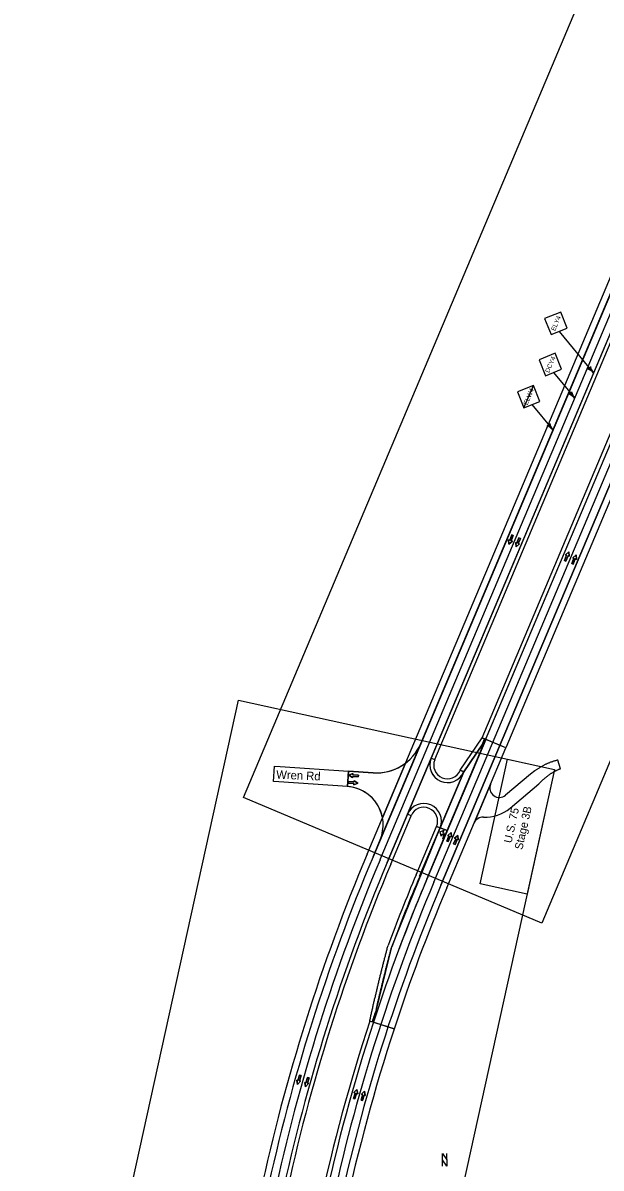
# Model space of a CAD drawing. Extents: x 14104283 to 14128447, y 8633203 to 8671666.
# Drawn here: x 14108596 to 14109499, y 8644945 to 8646734 of the extents above; entities that cross this region are included whole.
import ezdxf

# ---------------------------------------------------------------- set-up
doc = ezdxf.new("R2010")
doc.units = 0
for name, color, linetype in [('Cell', 7, 'Continuous'), ('Default', 7, 'Continuous'), ('dsnCellsNorthArrow', 7, 'Continuous'), ('dsnNonPlotable', 7, 'Continuous'), ('dsnPaintExistingBrokenLaneLineWhite', 7, 'Continuous'), ('dsnPaintExistingEdgeLineRightWhite', 7, 'Continuous'), ('dsnPaintExistingLaneLineWhite', 7, 'Continuous'), ('dsnPaintPlaceBrokenLineWhite', 7, 'Continuous'), ('dsnPaintPlaceEdgeLineLeftYellow', 7, 'Continuous'), ('dsnPaintPlaceEdgeLineRightWhite', 7, 'Continuous'), ('dsnShadingGranular', 7, 'Continuous'), ('dsnShadingPaved', 7, 'Continuous'), ('dsnStdLabel', 7, 'Continuous'), ('dsnStgShadingPrevPav', 7, 'Continuous'), ('dsnTextFinalPlan', 7, 'Continuous'), ('dsnTextOverlapEven', 7, 'Continuous')]:
    doc.layers.add(name, color=color, linetype=linetype)

msp = doc.modelspace()

# ---------------------------------------------------------------- linework, layer by layer
at = {"layer": 'Cell'}
for p, q in [((14109251.5, 8645469.4), (14109251.7, 8645469.4)), ((14109250.7, 8645466.9), (14109250.4, 8645467))]:
    msp.add_line(p, q, dxfattribs=at)
for points in [[(14109359.3, 8645933.9), (14109361.6, 8645933), (14109358.3, 8645924.9), (14109360.1, 8645924.2), (14109354.8, 8645919.6), (14109354.3, 8645926.5), (14109356, 8645925.8)], [(14109370.3, 8645929.5), (14109372.7, 8645928.6), (14109369.3, 8645920.5), (14109371.1, 8645919.8), (14109365.8, 8645915.2), (14109365.3, 8645922.2), (14109367, 8645921.4)], [(14109443.7, 8645893.2), (14109441.4, 8645894.2), (14109444.7, 8645902.3), (14109442.9, 8645903), (14109448.2, 8645907.6), (14109448.7, 8645900.6), (14109447, 8645901.3)], [(14109455, 8645888.4), (14109452.7, 8645889.4), (14109456, 8645897.5), (14109454.3, 8645898.2), (14109459.5, 8645902.8), (14109460.1, 8645895.8), (14109458.3, 8645896.5)], [(14109119.8, 8645558.6), (14109119.6, 8645556.1), (14109110.9, 8645556.8), (14109110.7, 8645554.9), (14109104.8, 8645558.6), (14109111.2, 8645561.2), (14109111.1, 8645559.3)], [(14109103.8, 8645546.5), (14109104, 8645549), (14109112.7, 8645548.3), (14109112.9, 8645550.1), (14109118.9, 8645546.5), (14109112.4, 8645543.9), (14109112.5, 8645545.8)], [(14109259.9, 8645454.9), (14109257.6, 8645455.8), (14109260.9, 8645463.9), (14109259.2, 8645464.6), (14109264.4, 8645469.2), (14109265, 8645462.3), (14109263.2, 8645463)], [(14109270.7, 8645450.4), (14109268.4, 8645451.3), (14109271.7, 8645459.4), (14109270, 8645460.1), (14109275.2, 8645464.7), (14109275.7, 8645457.7), (14109274, 8645458.5)], [(14109027.8, 8645090.4), (14109030.2, 8645089.7), (14109027.7, 8645081.3), (14109029.5, 8645080.7), (14109024.8, 8645075.6), (14109023.5, 8645082.5), (14109025.3, 8645082)], [(14109040.4, 8645086.8), (14109042.8, 8645086.1), (14109040.3, 8645077.7), (14109042.1, 8645077.2), (14109037.4, 8645072.1), (14109036.1, 8645078.9), (14109037.9, 8645078.4)], [(14109114.4, 8645053.2), (14109112, 8645054), (14109114.5, 8645062.3), (14109112.7, 8645062.9), (14109117.4, 8645068), (14109118.7, 8645061.1), (14109116.9, 8645061.6)], [(14109126.3, 8645050.6), (14109123.9, 8645051.3), (14109126.3, 8645059.7), (14109124.5, 8645060.3), (14109129.3, 8645065.4), (14109130.5, 8645058.5), (14109128.7, 8645059)]]:
    msp.add_lwpolyline(points, close=True, dxfattribs=at)
for points in [[(14109356, 8645925.8), (14109354.3, 8645926.5), (14109354.8, 8645919.6), (14109360.1, 8645924.2), (14109358.3, 8645924.9), (14109361.6, 8645933), (14109359.3, 8645933.9), (14109356, 8645925.8)], [(14109367, 8645921.4), (14109365.3, 8645922.2), (14109365.8, 8645915.2), (14109371.1, 8645919.8), (14109369.3, 8645920.5), (14109372.7, 8645928.6), (14109370.3, 8645929.5), (14109367, 8645921.4)], [(14109447, 8645901.3), (14109448.7, 8645900.6), (14109448.2, 8645907.6), (14109442.9, 8645903), (14109444.7, 8645902.3), (14109441.4, 8645894.2), (14109443.7, 8645893.2), (14109447, 8645901.3)], [(14109458.3, 8645896.5), (14109460.1, 8645895.8), (14109459.5, 8645902.8), (14109454.3, 8645898.2), (14109456, 8645897.5), (14109452.7, 8645889.4), (14109455, 8645888.4), (14109458.3, 8645896.5)], [(14109111.1, 8645559.3), (14109111.2, 8645561.2), (14109104.8, 8645558.6), (14109110.7, 8645554.9), (14109110.9, 8645556.8), (14109119.6, 8645556.1), (14109119.8, 8645558.6), (14109111.1, 8645559.3)], [(14109112.5, 8645545.8), (14109112.4, 8645543.9), (14109118.9, 8645546.5), (14109112.9, 8645550.1), (14109112.7, 8645548.3), (14109104, 8645549), (14109103.8, 8645546.5), (14109112.5, 8645545.8)], [(14109247.3, 8645470.5), (14109253, 8645472.8), (14109251.5, 8645469.4)], [(14109247.3, 8645470.5), (14109253, 8645472.8), (14109251.5, 8645469.4)], [(14109250.4, 8645467), (14109248.8, 8645463.7), (14109247.3, 8645470.5)], [(14109250.4, 8645467), (14109248.8, 8645463.7), (14109247.3, 8645470.5)], [(14109251.5, 8645469.4), (14109251.7, 8645469.4)], [(14109263.2, 8645463), (14109265, 8645462.3), (14109264.4, 8645469.2), (14109259.2, 8645464.6), (14109260.9, 8645463.9), (14109257.6, 8645455.8), (14109259.9, 8645454.9), (14109263.2, 8645463)], [(14109250.7, 8645466.9), (14109250.4, 8645467)], [(14109254.3, 8645462.6), (14109252.9, 8645459.2), (14109251.5, 8645459.8), (14109252.5, 8645462.2)], [(14109254.3, 8645462.6), (14109252.9, 8645459.2), (14109251.5, 8645459.8), (14109252.5, 8645462.2)], [(14109274, 8645458.5), (14109275.7, 8645457.7), (14109275.2, 8645464.7), (14109270, 8645460.1), (14109271.7, 8645459.4), (14109268.4, 8645451.3), (14109270.7, 8645450.4), (14109274, 8645458.5)], [(14109025.3, 8645082), (14109023.5, 8645082.5), (14109024.8, 8645075.6), (14109029.5, 8645080.7), (14109027.7, 8645081.3), (14109030.2, 8645089.7), (14109027.8, 8645090.4), (14109025.3, 8645082)], [(14109037.9, 8645078.4), (14109036.1, 8645078.9), (14109037.4, 8645072.1), (14109042.1, 8645077.2), (14109040.3, 8645077.7), (14109042.8, 8645086.1), (14109040.4, 8645086.8), (14109037.9, 8645078.4)], [(14109116.9, 8645061.6), (14109118.7, 8645061.1), (14109117.4, 8645068), (14109112.7, 8645062.9), (14109114.5, 8645062.3), (14109112, 8645054), (14109114.4, 8645053.2), (14109116.9, 8645061.6)], [(14109128.7, 8645059), (14109130.5, 8645058.5), (14109129.3, 8645065.4), (14109124.5, 8645060.3), (14109126.3, 8645059.7), (14109123.9, 8645051.3), (14109126.3, 8645050.6), (14109128.7, 8645059)]]:
    msp.add_lwpolyline(points, dxfattribs=at)
for centre, major_axis in [((14109249.7, 8645464.5), (-1.97, -4.87)), ((14109249.7, 8645464.5), (-1.97, -4.87)), ((14109249.3, 8645463.5), (-1.38, -3.41)), ((14109249.3, 8645463.5), (-1.38, -3.41))]:
    msp.add_ellipse(centre, major_axis=major_axis, ratio=0.9474, start_param=1.570796, end_param=3.141593, dxfattribs=at)
at = {"layer": 'Default'}
for points in [[(14118413.2, 8667444.3), (14110818.4, 8649409.2), (14109142.6, 8645431.4)], [(14109164.7, 8645422.1), (14110840.5, 8649399.8), (14118435.4, 8667434.9)]]:
    msp.add_lwpolyline(points, dxfattribs=at)
for radius in [2968, 2944]:
    msp.add_arc((14111877.8, 8644279.1), radius, 157.1547, 167.8488, dxfattribs=at)
at = {"layer": 'dsnCellsNorthArrow'}
msp.add_lwpolyline([(14109257.8, 8644947.9), (14109250.8, 8644957.7), (14109250.8, 8644967.6), (14109257.8, 8644957.7)], close=True, dxfattribs=at)
msp.add_lwpolyline([(14109250.8, 8644947.9), (14109250.8, 8644967.6), (14109257.8, 8644957.7), (14109257.8, 8644967.6)], dxfattribs=at)
at = {"layer": 'dsnNonPlotable'}
for points in [[(14108940.5, 8645523.8), (14109549.1, 8646968.3), (14110014.5, 8646772.2), (14109405.9, 8645327.7)], [(14108596.1, 8644144.9), (14108932.5, 8645675.8), (14109425.7, 8645567.5), (14109089.3, 8644036.5)]]:
    msp.add_lwpolyline(points, close=True, dxfattribs=at)
at = {"layer": 'dsnPaintExistingBrokenLaneLineWhite'}
msp.add_line((14109153.7, 8645426.8), (14110829.5, 8649404.5), dxfattribs=at)
msp.add_arc((14111877.8, 8644279.1), 2956, 157.1547, 167.8488, dxfattribs=at)
at = {"layer": 'dsnPaintExistingEdgeLineRightWhite'}
msp.add_line((14109155.3, 8645461.5), (14109142.6, 8645431.4), dxfattribs=at)
msp.add_lwpolyline([(14111344.6, 8650658.6), (14110818.4, 8649409.2), (14109217, 8645608.1)], dxfattribs=at)
msp.add_arc((14111877.8, 8644279.1), 2968, 157.1547, 167.8488, dxfattribs=at)
at = {"layer": 'dsnPaintExistingLaneLineWhite'}
msp.add_line((14109226.5, 8645396.1), (14109258.5, 8645472.2), dxfattribs=at)
msp.add_arc((14111877.8, 8644279.1), 2877, 157.1547, 159.5027, dxfattribs=at)
at = {"layer": 'dsnPaintPlaceBrokenLineWhite'}
msp.add_line((14109237.5, 8645391.4), (14110075.4, 8647380.3), dxfattribs=at)
msp.add_arc((14111877.8, 8644279.1), 2865, 157.1547, 167.8488, dxfattribs=at)
at = {"layer": 'dsnPaintPlaceEdgeLineLeftYellow'}
for p, q in [((14109318.3, 8645614.1), (14110902.3, 8649373.8)), ((14109283.6, 8645562.9), (14109318.3, 8645614.1)), ((14109196.6, 8645497.8), (14109164.7, 8645422.1)), ((14109171.7, 8645290.7), (14109247.3, 8645476.4)), ((14109143.1, 8645172.8), (14109171.7, 8645290.7))]:
    msp.add_line(p, q, dxfattribs=at)
msp.add_lwpolyline([(14111383.6, 8650689.4), (14110840.5, 8649399.8), (14109233.5, 8645585.3)], dxfattribs=at)
for centre, radius, start, end in [((14109258.8, 8645574.6), 27.5, 157.1547, 335.8415), ((14109221.9, 8645487.1), 27.5, 67.1547, 157.1547), ((14109221.9, 8645487.1), 27.5, 337.1547, 67.1547), ((14111877.8, 8644279.1), 2944, 157.1547, 167.8488), ((14111877.8, 8644279.1), 2877, 161.903, 167.8488)]:
    msp.add_arc(centre, radius, start, end, dxfattribs=at)
at = {"layer": 'dsnPaintPlaceEdgeLineRightWhite'}
msp.add_line((14109248.6, 8645386.8), (14110924.4, 8649364.5), dxfattribs=at)
msp.add_arc((14111877.8, 8644279.1), 2853, 157.1547, 167.8488, dxfattribs=at)
at = {"layer": 'dsnShadingGranular'}
msp.add_line((14109326, 8645544.7), (14109300.4, 8645484), dxfattribs=at)
at = {"layer": 'dsnShadingPaved'}
for p, q in [((14109258.5, 8645472.2), (14110902.3, 8649373.8)), ((14110924.4, 8649364.5), (14109248.6, 8645386.8)), ((14109318.3, 8645614.1), (14109258.5, 8645472.2)), ((14109283.6, 8645562.9), (14109318.3, 8645614.1)), ((14109153.7, 8645457.8), (14109217, 8645608.1)), ((14109196.6, 8645497.8), (14109233.5, 8645585.3)), ((14109104.1, 8645564.9), (14109102.5, 8645541)), ((14109142.9, 8645562.3), (14109104.1, 8645564.9)), ((14109171.7, 8645290.7), (14109247.3, 8645476.4)), ((14109247.3, 8645476.4), (14109258.5, 8645472.2)), ((14109258.5, 8645472.2), (14109247.3, 8645476.4)), ((14109143.1, 8645172.8), (14109171.7, 8645290.7))]:
    msp.add_line(p, q, dxfattribs=at)
for centre, radius, start, end in [((14109147.9, 8645637.2), 75, 266.1547, 337.1547), ((14109258.8, 8645574.6), 27.5, 157.1547, 247.1547), ((14109258.8, 8645574.6), 27.5, 247.1547, 335.8415), ((14109098.4, 8645481.1), 60, 337.1547, 86.1547), ((14109221.9, 8645487.1), 27.5, 67.1547, 157.1547), ((14109221.9, 8645487.1), 27.5, 337.1547, 67.1547), ((14111877.8, 8644279.1), 2853, 157.1547, 167.8488), ((14111877.8, 8644279.1), 2877, 161.903, 167.8488)]:
    msp.add_arc(centre, radius, start, end, dxfattribs=at)
at = {"layer": 'dsnStdLabel'}
for p, q in [((14109433.2, 8646251.9), (14109486.9, 8646186.8)), ((14109424.4, 8646187.6), (14109457.4, 8646147.6)), ((14109378.2, 8646132.4), (14109393.1, 8646167.6)), ((14109390.7, 8646137.5), (14109423.4, 8646097.9))]:
    msp.add_line(p, q, dxfattribs=at)
for points in [[(14109420.7, 8646246.8), (14109445.7, 8646257), (14109435.5, 8646282), (14109410.5, 8646271.9)], [(14109411.9, 8646182.5), (14109436.9, 8646192.7), (14109426.7, 8646217.7), (14109401.7, 8646207.5)], [(14109378.2, 8646132.4), (14109403.2, 8646142.5), (14109393.1, 8646167.6), (14109368.1, 8646157.4)]]:
    msp.add_lwpolyline(points, close=True, dxfattribs=at)
for centre, radius, start, end in [((14109474.4, 8646201.4), 8.86, 292.8385, 328.307), ((14109469.5, 8646171.9), 22.9, 40.5727, 68.6439), ((14109504.3, 8646201.8), 22.9, 192.5015, 220.5728), ((14109444.8, 8646162.2), 8.86, 292.8385, 328.307), ((14109439.9, 8646132.7), 22.9, 40.5727, 68.6439), ((14109474.8, 8646162.5), 22.9, 192.5015, 220.5728), ((14109410.9, 8646112.5), 8.86, 292.8385, 328.307), ((14109406, 8646083), 22.9, 40.5727, 68.6439), ((14109440.8, 8646112.8), 22.9, 192.5015, 220.5728)]:
    msp.add_arc(centre, radius, start, end, dxfattribs=at)
at = {"layer": 'dsnStgShadingPrevPav'}
for p, q in [((14109133.4, 8645435.3), (14110809.2, 8649413)), ((14110818.4, 8649409.2), (14109142.6, 8645431.4)), ((14109318.5, 8645614.6), (14109226.5, 8645396.1)), ((14109318.5, 8645614.6), (14109226.5, 8645396.1)), ((14109312.8, 8645606.2), (14109316.7, 8645615.4)), ((14109316.7, 8645615.4), (14109318.5, 8645614.6)), ((14109349.9, 8645601.4), (14109318.5, 8645614.6)), ((14109155.3, 8645461.5), (14109217, 8645608.1)), ((14109257.8, 8645382.9), (14109349.9, 8645601.4)), ((14109284.2, 8645564), (14109312.8, 8645606.2)), ((14109193.3, 8645577.5), (14109157.4, 8645492.3)), ((14109196.6, 8645497.8), (14109233.5, 8645585.3)), ((14109233.5, 8645585.3), (14109196.6, 8645497.8)), ((14109233.5, 8645585.3), (14109239, 8645583)), ((14109435.2, 8645568.8), (14109431.1, 8645582.2)), ((14109102.5, 8645541), (14109104.1, 8645564.9)), ((14109104.1, 8645564.9), (14109142.9, 8645562.3)), ((14109215.4, 8645400.8), (14109284.2, 8645564)), ((14109284.2, 8645564), (14109247.3, 8645476.4)), ((14109278.6, 8645566.3), (14109284.2, 8645564)), ((14109326, 8645544.7), (14109300.4, 8645484)), ((14109356.6, 8645507.3), (14109401.4, 8645545.2)), ((14109401.4, 8645545.2), (14109407.2, 8645550.9)), ((14109196.6, 8645497.8), (14109164.7, 8645422.1)), ((14109196.6, 8645497.8), (14109164.7, 8645422.1)), ((14109170.3, 8645419.8), (14109202.1, 8645495.4)), ((14109202.1, 8645495.4), (14109196.6, 8645497.8)), ((14109202.1, 8645495.4), (14109196.6, 8645497.8)), ((14109209.9, 8645403.1), (14109241.8, 8645478.7)), ((14109247.3, 8645476.4), (14109215.4, 8645400.8)), ((14109247.3, 8645476.4), (14109241.8, 8645478.7)), ((14109241.8, 8645478.7), (14109247.3, 8645476.4)), ((14109142.6, 8645431.4), (14109155.3, 8645461.5)), ((14109175.4, 8645162.3), (14109137.4, 8645174.7)), ((14109141.2, 8645173.4), (14109137.4, 8645174.7)), ((14109143.1, 8645172.8), (14109141.2, 8645173.4)), ((14109143.1, 8645172.8), (14109175.4, 8645162.3))]:
    msp.add_line(p, q, dxfattribs=at)
for points in [[(14109239, 8645583), (14111389.1, 8650687.1), (14111383.6, 8650689.4), (14109233.5, 8645585.3)], [(14109313, 8645616.9), (14110622.7, 8648725.7), (14110659.7, 8648710.5), (14109349.9, 8645601.4)], [(14109278.6, 8645566.3), (14109313, 8645616.9), (14109316.7, 8645615.4), (14109312.8, 8645606.2), (14109284.2, 8645564)], [(14108987.2, 8645548.7), (14108988.7, 8645572.7), (14108997.4, 8645572.1), (14109104.1, 8645564.9), (14109102.5, 8645541), (14108995.8, 8645548.2)]]:
    msp.add_lwpolyline(points, close=True, dxfattribs=at)
for points in [[(14111383.6, 8650689.4), (14110840.5, 8649399.8), (14109233.5, 8645585.3)], [(14109217, 8645608.1), (14110818.4, 8649409.2), (14111344.6, 8650658.6)], [(14109395, 8645565.3), (14109388.4, 8645560.5), (14109349.5, 8645527.5)]]:
    msp.add_lwpolyline(points, dxfattribs=at)
for centre, radius, start, end in [((14109147.9, 8645637.2), 75, 266.1547, 307.2283), ((14109258.8, 8645574.6), 21.5, 157.1547, 247.1547), ((14109258.8, 8645574.6), 21.5, 247.1547, 337.1547), ((14109098.4, 8645481.1), 60, 10.712, 86.1547), ((14109339.8, 8645538.9), 15, 157.1547, 310.2778), ((14109221.9, 8645487.1), 21.5, 67.1547, 157.1547), ((14109221.9, 8645487.1), 21.5, 337.1547, 67.1547), ((14109317.8, 8645553), 60, 267.2336, 310.2778), ((14109314.2, 8645478.1), 15, 87.2336, 157.1547), ((14111877.8, 8644279.1), 2978, 157.1547, 167.8488), ((14111877.8, 8644279.1), 2968, 157.1547, 167.8488), ((14111877.8, 8644279.1), 2968, 157.1547, 167.8488), ((14111877.8, 8644279.1), 2944, 157.1547, 167.8488), ((14111877.8, 8644279.1), 2944, 157.1547, 167.8488), ((14111877.8, 8644279.1), 2938, 157.1547, 167.8488), ((14111877.8, 8644279.1), 2877, 157.1547, 161.9025), ((14111877.8, 8644279.1), 2877, 157.1547, 161.9025), ((14111877.8, 8644279.1), 2895, 157.1547, 159.5027), ((14111877.8, 8644279.1), 2889, 157.1547, 159.5027), ((14111877.8, 8644279.1), 2889, 157.1547, 159.5027), ((14111877.8, 8644279.1), 2843, 157.1547, 161.9025), ((14111877.8, 8644279.1), 2879, 161.5026, 161.9025), ((14111877.8, 8644279.1), 2879, 161.5026, 161.9025), ((14111877.8, 8644279.1), 2883, 161.9025, 167.8488), ((14111877.8, 8644279.1), 2843, 161.9025, 167.8488)]:
    msp.add_arc(centre, radius, start, end, dxfattribs=at)
for points in [[(14109431.1, 8645582.2), (14109430.5, 8645582.1), (14109429.2, 8645581.8), (14109427.3, 8645581.3), (14109425.4, 8645580.7), (14109423.5, 8645580.1), (14109421.6, 8645579.5), (14109419.7, 8645578.8), (14109417.8, 8645578.1), (14109416, 8645577.3), (14109414.1, 8645576.5), (14109412.3, 8645575.7), (14109410.5, 8645574.8), (14109408.7, 8645573.9), (14109406.9, 8645573), (14109405.1, 8645572), (14109403.4, 8645571), (14109401.7, 8645569.9), (14109400, 8645568.8), (14109398.3, 8645567.7), (14109396.6, 8645566.5), (14109395.5, 8645565.7), (14109395, 8645565.3)], [(14109407.2, 8645550.9), (14109407.6, 8645551.3), (14109408.4, 8645552), (14109409.6, 8645553.1), (14109410.9, 8645554.2), (14109412.1, 8645555.3), (14109413.4, 8645556.4), (14109414.7, 8645557.4), (14109416, 8645558.4), (14109417.4, 8645559.4), (14109418.8, 8645560.3), (14109420.2, 8645561.2), (14109421.6, 8645562.1), (14109423, 8645563), (14109424.5, 8645563.8), (14109426, 8645564.6), (14109427.5, 8645565.4), (14109429, 8645566.2), (14109430.5, 8645566.9), (14109432, 8645567.6), (14109433.6, 8645568.2), (14109434.7, 8645568.6), (14109435.2, 8645568.8)], [(14109137.4, 8645174.7), (14109137.9, 8645176.7), (14109138.7, 8645180.6), (14109140.1, 8645186.5), (14109141.4, 8645192.5), (14109142.7, 8645198.4), (14109144.1, 8645204.3), (14109145.5, 8645210.2), (14109146.9, 8645216.1), (14109148.3, 8645222), (14109149.7, 8645228), (14109151.1, 8645233.9), (14109152.5, 8645239.8), (14109154, 8645245.7), (14109155.5, 8645251.6), (14109156.9, 8645257.5), (14109158.4, 8645263.4), (14109159.9, 8645269.3), (14109161.5, 8645275.2), (14109163, 8645281.1), (14109164.5, 8645287), (14109165.6, 8645290.9), (14109166.1, 8645292.8)], [(14109147.5, 8645192.5), (14109147.9, 8645194.2), (14109148.7, 8645197.4), (14109149.8, 8645202.4), (14109150.9, 8645207.3), (14109152.1, 8645212.2), (14109153.2, 8645217.1), (14109154.4, 8645222), (14109155.6, 8645227), (14109156.8, 8645231.9), (14109158, 8645236.8), (14109159.2, 8645241.7), (14109160.4, 8645246.6), (14109161.6, 8645251.5), (14109162.8, 8645256.4), (14109164.1, 8645261.3), (14109165.3, 8645266.2), (14109166.6, 8645271.1), (14109167.8, 8645276), (14109169.1, 8645281), (14109170.4, 8645285.9), (14109171.3, 8645289.1), (14109171.7, 8645290.7)], [(14109171.7, 8645290.7), (14109171.3, 8645289.1), (14109170.4, 8645285.9), (14109169.1, 8645281), (14109167.8, 8645276), (14109166.6, 8645271.1), (14109165.3, 8645266.2), (14109164.1, 8645261.3), (14109162.8, 8645256.4), (14109161.6, 8645251.5), (14109160.4, 8645246.6), (14109159.2, 8645241.7), (14109158, 8645236.8), (14109156.8, 8645231.9), (14109155.6, 8645227), (14109154.4, 8645222), (14109153.2, 8645217.1), (14109152.1, 8645212.2), (14109150.9, 8645207.3), (14109149.8, 8645202.4), (14109148.7, 8645197.4), (14109147.9, 8645194.2), (14109147.5, 8645192.5)]]:
    msp.add_open_spline(points, degree=3, dxfattribs=at)
at = {"layer": 'dsnTextOverlapEven'}
for points in [[(14109425.7, 8645567.5), (14109383, 8645372.8), (14109309.7, 8645388.9), (14109352.5, 8645583.6)], [(14109309.7, 8645388.9), (14109352.5, 8645583.6), (14109425.7, 8645567.5), (14109383, 8645372.8)]]:
    msp.add_lwpolyline(points, close=True, dxfattribs=at)

# ---------------------------------------------------------------- texts
at = {"layer": 'dsnStdLabel'}
for s, p in [('ELY4', (14109426.7, 8646251.9)), ('DCY4', (14109417.5, 8646186.5)), ('ELW4', (14109383.7, 8646136.2))]:
    msp.add_text(s, height=7.2, rotation=67.1547, dxfattribs=at).set_placement(p)
at = {"layer": 'dsnTextFinalPlan'}
msp.add_text('Wren Rd', height=13.12, rotation=357.6374, dxfattribs=at).set_placement((14108991.3, 8645553.3))
at = {"layer": 'dsnTextOverlapEven'}
for s, p in [('U.S. 75', (14109358.7, 8645451.9)), ('Stage 3B', (14109375.7, 8645441.5))]:
    msp.add_text(s, height=12.5, rotation=77.6078, dxfattribs=at).set_placement(p)

doc.saveas('drawing.dxf')
